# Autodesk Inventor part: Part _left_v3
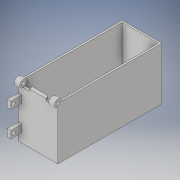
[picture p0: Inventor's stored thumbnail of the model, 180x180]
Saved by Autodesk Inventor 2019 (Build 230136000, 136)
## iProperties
Created: 2019-08
Part Number: Part _left_v3
Material: 常规
Document SubType Name: Modeling
Designer: YOGA3
Density: 1 g/cm^3
Appearance: 默认
Author: YOGA3
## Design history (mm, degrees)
sketch "草图1"
  geometry: L1 (-22, 57.5)-(22, 57.5); L2 (22, 57.5)-(22, -57.5); L3 (22, -57.5)-(-22, -57.5); L4 (-22, -57.5)-(-22, 57.5); L5 (-22, 57.5)-(22, -57.5); L6 (22, 57.5)-(-22, -57.5); 1 further point
  constraints: 12 end point, 2 midpoint, 2 parallel, 1 horizontal, 1 perpendicular
  dimensions: "d0" = 44 distance of L2.end L3.end; "d1" = 115 distance of L1.end L2.end
extrude "拉伸1" new body sketch "草图1" distance "d2" = 58; taper "d3" = 0 deg
sketch "草图2"
  geometry: L1 (20, 55.5)-(-20, 55.5); L2 (-20, 55.5)-(-20, -55.5); L3 (-20, -55.5)-(20, -55.5); L4 (20, -55.5)-(20, 55.5); L5 (20, 55.5)-(-20, -55.5); L6 (-20, 55.5)-(20, -55.5); 1 further point
  constraints: 12 end point, 2 midpoint, 2 parallel, 1 horizontal, 1 perpendicular
  dimensions: "d4" = 40 distance of L3.end L2.end; "d5" = 111 distance of L1.end L2.end
extrude "拉伸2" cut sketch "草图2" distance "d6" = 56; taper "d7" = 0 deg
sketch "草图3"
  geometry: L1 (-22, -57.5)-(22, -57.5) reference; L2 (20, 55.5)-(20, -55.5) reference; C1 r 2 at (14, -12.5); C2 r 2 at (-10, -12.5); 1 further point
  constraints: 2 centre point
  dimensions: "d8" = 4 diameter of C1; "d9" = 4 diameter of C2; "d10" = 45 distance from line of L1 C1.centre; "d11" = 45 distance from line of C2.centre L1; "d12" = 24 distance of C1.centre C2.centre; "d13" = 6 distance from line of L2 C1.centre
extrude "拉伸3" join sketch "草图3" distance "d14" = 6; taper "d15" = 0 deg
mirror "镜像1"
sketch "草图4"
  geometry: L1 (22.25, 25.5)-(1.75, 25.5); L2 (-0.25, 23.5)-(-0.25, 1.5); L3 (1.75, -0.5)-(22.25, -0.5); L4 (24.25, 1.5)-(24.25, 23.5); L5 (24.25, 25.5)-(-0.25, -0.5); L6 (-0.25, 25.5)-(24.25, -0.5); L7 (-12, -45)-(32, -45) reference; L8 (30, 68)-(30, -43) reference; A1 r 2 centre (22.25, 1.5) between (22.25, -0.5) and (24.25, 1.5); A2 r 2 centre (22.25, 23.5) between (24.25, 23.5) and (22.25, 25.5); A3 r 2 centre (1.75, 23.5) between (1.75, 25.5) and (-0.25, 23.5); A4 r 2 centre (1.75, 1.5) between (-0.25, 1.5) and (1.75, -0.5); 2 further points
  constraints: 12 end point, 8 point on circle, 8 point on line, 8 tangent, 4 centre point, 3 equal radius, 2 midpoint, 2 parallel, 1 horizontal, 1 perpendicular
  dimensions: "d16" = 24.5 distance of L5.end L6.end; "d17" = 26 distance of L6.start L5.end; "d18" = 44.5 distance between parallel lines of L7 L3; "d19" = 18 distance from line of L8 point (12, 12.5); "d20" = 2 radius of A1 (derived)
extrude "拉伸4" cut sketch "草图4" distance "d21" = 2.5; taper "d22" = 0 deg
sketch "草图5"
  geometry: L1 (115, 58)-(0, 58) reference; C1 r 2 at (0, 58); 1 further point
  constraints: 1 centre point
  dimensions: "d23" = 4 diameter of C1
extrude "拉伸5" cut sketch "草图5" distance "d24" = 44; taper "d25" = 0 deg
sketch "草图6"
  geometry: C1 r 4 at (0, 58); A1 r 2 centre (0, 58) between (0, 56) and (2, 58) reference; 2 further points
  constraints: 2 coincident, 1 centre point, 1 horizontal alignment, 2 other
  dimensions: "d26" = 8 diameter of C1
extrude "拉伸6" join sketch "草图6" distance "d27" = 6; taper "d28" = 0 deg
sketch "草图7"
  geometry: C1 r 2 at (115, 58); C2 r 4 at (115, 58); A1 r 2 centre (115, 58) between (115, 56) and (113, 58) reference; 1 further point
  constraints: 2 centre point, 2 coincident
extrude "拉伸7" join sketch "草图7" distance "d29" = 6; taper "d30" = 0 deg
sketch "草图8"
  geometry: C1 r 4 at (-115, 58); A1 r 4 centre (-115, 58) between (-111, 58) and (-115, 54) reference; 1 further point
  constraints: 1 centre point, 1 coincident
extrude "拉伸8" cut sketch "草图8" distance "d31" = 7; taper "d32" = 0 deg
sketch "草图9"
  geometry: A1 r 4 centre (0, 58) between (0, 54) and (-4, 58) reference; 2 further points
  constraints: 1 coincident, 1 horizontal alignment, 2 other
extrude "拉伸9" cut sketch "草图9" distance "d33" = 7; taper "d34" = 0 deg
sketch "草图10"
  geometry: L1 (47.5, 4.8)-(67.5, 4.8); L2 (67.5, 4.8)-(67.5, 4); L3 (67.5, 4)-(47.5, 4); L4 (47.5, 4)-(47.5, 4.8); L5 (47.5, 4.8)-(67.5, 4); L6 (67.5, 4.8)-(47.5, 4); L7 (115, 0)-(0, 0) reference; 2 further points
  constraints: 12 end point, 2 midpoint, 2 parallel, 1 horizontal, 1 perpendicular
  dimensions: "d35" = 20 distance of L2.end L3.end; "d36" = 0.8 distance of L1.end L2.end; "d37" = 4 distance between parallel lines of L7 L3
extrude "拉伸10" cut sketch "草图10" distance "d38" = 2; taper "d39" = 0 deg
sketch "草图11"
  geometry: L1 (0, 58)-(111, 58) reference; L2 (115, 0)-(115, 54) reference; C1 r 3 at (109, 53); 1 further point
  constraints: 1 centre point
  dimensions: "d40" = 6 diameter of C1; "d41" = 5 distance from line of L1 C1.centre; "d42" = 6 distance from line of L2 C1.centre
extrude "拉伸11" cut sketch "草图11" distance "d43" = 2; taper "d44" = 0 deg
sketch "草图12"
  geometry: L1 (115, 38)-(127, 38); L2 (127, 38)-(127, 46); L3 (127, 46)-(115, 46); L4 (115, 46)-(115, 38); L5 (115, 38)-(127, 46); L6 (127, 38)-(115, 46); L7 (115, 18)-(127, 18); L8 (127, 18)-(127, 10); L9 (127, 10)-(115, 10); L10 (115, 10)-(115, 18); L11 (115, 18)-(127, 10); L12 (127, 18)-(115, 10); L13 (115, 0)-(115, 54) reference; L14 (115, 0)-(0, 0) reference; C1 r 2 at (124, 42); C2 r 2 at (124, 14); 3 further points
  constraints: 24 end point, 4 midpoint, 4 parallel, 2 centre point, 2 horizontal, 2 perpendicular
  dimensions: "d45" = 12 distance of L3.end L2.end; "d46" = 8 distance of L2.end L1.end; "d47" = 12 distance of L8.end L9.end; "d48" = 8 distance of L7.end L8.end; "d49" = 0 distance between parallel lines of L13 L4; "d50" = 0 distance between parallel lines of L13 L10; "d51" = 10 distance between parallel lines of L14 L9; "d52" = 38 distance between parallel lines of L14 L1; "d53" = 4 diameter of C1; "d54" = 4 diameter of C2; "d55" = 3 distance from line of L2 C1.centre; "d56" = 3 distance from line of L8 C2.centre
extrude "拉伸12" join sketch "草图12" distance "d57" = 4; taper "d58" = 0 deg
mirror "镜像2"
node "实体1"
